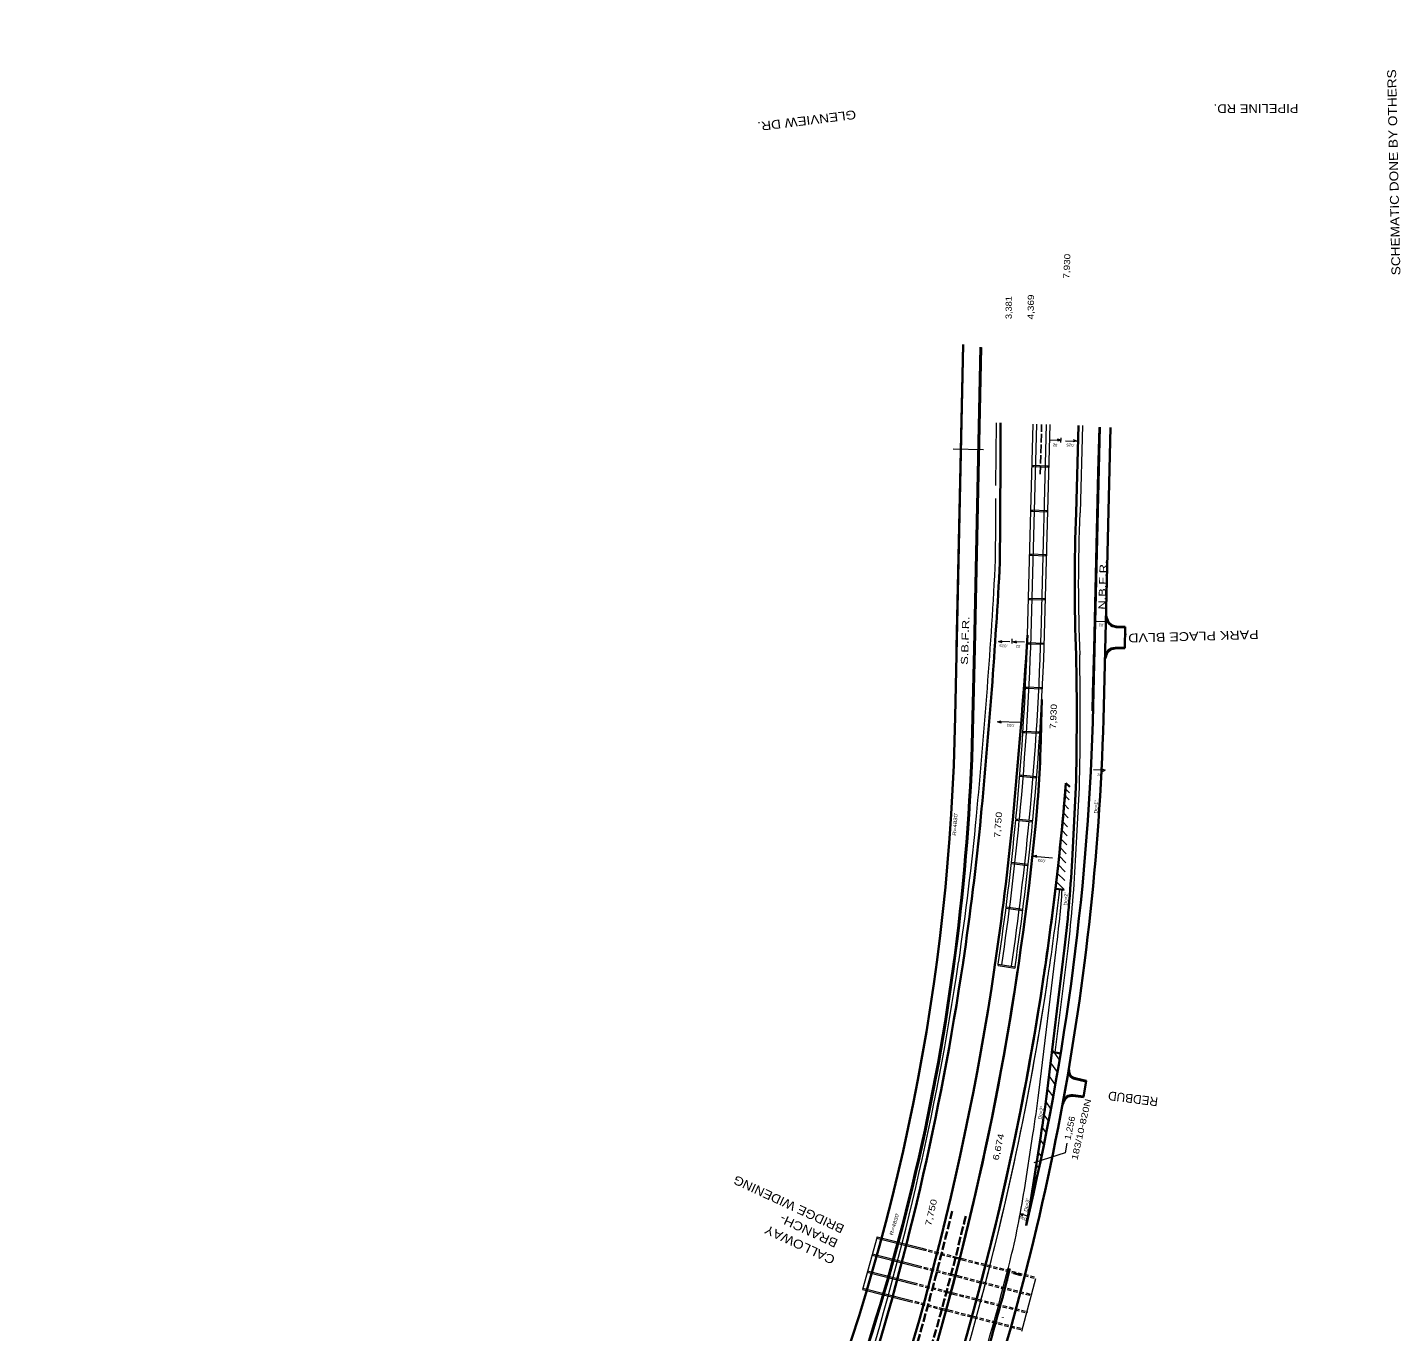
# Model space of a CAD drawing. Extents: x 2354993 to 2372084, y 6966390 to 6990057.
# Drawn here: x 2364099 to 2367196, y 6983254 to 6986197 of the extents above; entities that cross this region are included whole.
import ezdxf

# ---------------------------------------------------------------- set-up
doc = ezdxf.new("R2010")
doc.units = 0
doc.header["$LTSCALE"] = 3.2
doc.linetypes.add('LONG_DASHED', pattern=[7.5, 6, -1.5])
doc.linetypes.add('MEDIUM_DASHED', pattern=[4.5, 3, -1.5])
for name, color, linetype, lineweight in [('1', 7, 'Continuous', 13), ('11', 7, 'Continuous', 13), ('12', 7, 'Continuous', 13), ('13', 7, 'Continuous', 13), ('19', 7, 'Continuous', 13), ('2', 7, 'Continuous', 35), ('4', 7, 'Continuous', 13), ('40', 7, 'Continuous', 35), ('5', 7, 'Continuous', 35), ('6', 7, 'Continuous', 35), ('63', 7, 'Continuous', 35), ('7', 7, 'Continuous', 13), ('8', 7, 'Continuous', 13), ('9', 7, 'Continuous', 13)]:
    doc.layers.add(name, color=color, linetype=linetype, lineweight=lineweight)

msp = doc.modelspace()

# ---------------------------------------------------------------- linework, layer by layer
at = {"layer": '1', "lineweight": 35}
for p, q in [((2366503.056, 6984666.009), (2366518.337, 6985295.092)), ((2366527.049, 6984665.426), (2366542.33, 6985294.509))]:
    msp.add_line(p, q, dxfattribs=at)
at = {"layer": '1'}
for p, q in [((2366464.165, 6984330.073), (2366472.106, 6984481.877)), ((2366417.588, 6983883.842), (2366446.247, 6984118.848))]:
    msp.add_line(p, q, dxfattribs=at)
for points in [[(2366504.178, 6984794.577), (2366506.607, 6984894.547), (2366509.035, 6984994.518), (2366511.463, 6985094.488), (2366513.892, 6985194.459), (2366516.32, 6985294.429)], [(2366500.792, 6984655.165), (2366501.75, 6984694.606), (2366504.178, 6984794.577)]]:
    msp.add_lwpolyline(points, dxfattribs=at)
for centre, radius, start, end in [((2370574.042, 6984940.976), 4104.509, 177.76241, 182.23376), ((2359312.852, 6984644.469), 7161.104, 358.6944, 1.09115), ((2363580.688, 6984468.307), 2886.789, 353.04704, 357.25725), ((2359877.328, 6985028.057), 6596.25, 337.9611, 351.54396)]:
    msp.add_arc(centre, radius, start, end, dxfattribs=at)
at = {"layer": '1', "lineweight": 35}
msp.add_arc((2360811.157, 6984804.27), 5681.578, 345.37481, 345.37817, dxfattribs=at)
at = {"layer": '11'}
for p, q in [((2366538.791, 6984856.255), (2366530.724, 6984854.262)), ((2366529.954, 6984521.156), (2366503.645, 6984521.922)), ((2366523.004, 6984523.998), (2366529.954, 6984521.156)), ((2366523.876, 6984518.238), (2366529.954, 6984521.156))]:
    msp.add_line(p, q, dxfattribs=at)
msp.add_lwpolyline([(2366510.454, 6984857.25), (2366538.791, 6984856.255), (2366530.884, 6984858.81)], dxfattribs=at)
at = {"layer": '12'}
for p, q in [((2366364.888, 6985208.936), (2366364.805, 6985205.936)), ((2366364.805, 6985205.936), (2366403.044, 6985204.915)), ((2366364.888, 6985208.936), (2366403.118, 6985207.914)), ((2366367.987, 6985208.85), (2366367.904, 6985205.85)), ((2366399.945, 6985204.992), (2366400.019, 6985207.991)), ((2366403.044, 6985204.915), (2366403.118, 6985207.914)), ((2366362.436, 6985108.243), (2366362.353, 6985105.243)), ((2366362.353, 6985105.243), (2366400.592, 6985104.222)), ((2366362.436, 6985108.243), (2366400.666, 6985107.221)), ((2366365.535, 6985108.157), (2366365.452, 6985105.157)), ((2366397.493, 6985104.299), (2366397.567, 6985107.298)), ((2366400.592, 6985104.222), (2366400.666, 6985107.221)), ((2366359.998, 6985008.861), (2366359.915, 6985005.861)), ((2366359.915, 6985005.861), (2366398.154, 6985004.84)), ((2366359.998, 6985008.861), (2366398.228, 6985007.839)), ((2366363.097, 6985008.775), (2366363.014, 6985005.775)), ((2366395.055, 6985004.917), (2366395.129, 6985007.916)), ((2366398.154, 6985004.84), (2366398.228, 6985007.839)), ((2366357.049, 6984909.117), (2366356.966, 6984906.117)), ((2366356.966, 6984906.117), (2366395.205, 6984905.096)), ((2366357.049, 6984909.117), (2366395.279, 6984908.095)), ((2366360.148, 6984909.031), (2366360.065, 6984906.031)), ((2366392.106, 6984905.173), (2366392.18, 6984908.172)), ((2366395.205, 6984905.096), (2366395.279, 6984908.095)), ((2366354.588, 6984808.904), (2366354.505, 6984805.904)), ((2366354.505, 6984805.904), (2366392.744, 6984804.883)), ((2366354.588, 6984808.904), (2366392.818, 6984807.882)), ((2366357.687, 6984808.818), (2366357.604, 6984805.818)), ((2366389.645, 6984804.96), (2366389.719, 6984807.959)), ((2366392.744, 6984804.883), (2366392.818, 6984807.882)), ((2366350.209, 6984708.655), (2366350.126, 6984705.655)), ((2366350.126, 6984705.655), (2366388.365, 6984704.634)), ((2366350.209, 6984708.655), (2366388.439, 6984707.633)), ((2366353.308, 6984708.569), (2366353.225, 6984705.569)), ((2366385.266, 6984704.711), (2366385.34, 6984707.71)), ((2366388.365, 6984704.634), (2366388.439, 6984707.633)), ((2366344.53, 6984608.98), (2366344.406, 6984605.981)), ((2366344.406, 6984605.981), (2366382.629, 6984604.439)), ((2366344.53, 6984608.98), (2366382.743, 6984607.436)), ((2366347.628, 6984608.852), (2366347.504, 6984605.853)), ((2366379.531, 6984604.558), (2366379.646, 6984607.555)), ((2366382.629, 6984604.439), (2366382.743, 6984607.436)), ((2366338.161, 6984510.231), (2366337.864, 6984507.244)), ((2366338.161, 6984510.231), (2366376.221, 6984506.482)), ((2366341.246, 6984509.924), (2366340.949, 6984506.937)), ((2366337.864, 6984507.244), (2366375.933, 6984503.496)), ((2366372.847, 6984503.794), (2366373.135, 6984506.78)), ((2366375.933, 6984503.496), (2366376.221, 6984506.482)), ((2366328.743, 6984410.781), (2366328.446, 6984407.794)), ((2366328.446, 6984407.794), (2366366.515, 6984404.046)), ((2366328.743, 6984410.781), (2366366.803, 6984407.032)), ((2366331.828, 6984410.474), (2366331.531, 6984407.487)), ((2366363.429, 6984404.344), (2366363.717, 6984407.33)), ((2366366.515, 6984404.046), (2366366.803, 6984407.032)), ((2366318.344, 6984310.299), (2366356.373, 6984306.191)), ((2366318.666, 6984313.282), (2366356.695, 6984309.174)), ((2366306.287, 6984209.38), (2366344.232, 6984204.566)), ((2366306.665, 6984212.356), (2366344.611, 6984207.542)), ((2366288.504, 6984080.134), (2366288.942, 6984083.102)), ((2366288.504, 6984080.134), (2366326.343, 6984074.539)), ((2366288.942, 6984083.102), (2366326.781, 6984077.507)), ((2366326.781, 6984077.507), (2366326.343, 6984074.539)), ((2366015.164, 6983465.056), (2366116.698, 6983439.228)), ((2366015.904, 6983467.964), (2366117.457, 6983442.131)), ((2366004.286, 6983426.55), (2366106.578, 6983400.527)), ((2366005.097, 6983429.441), (2366107.337, 6983403.431)), ((2366186.244, 6983424.631), (2366208.214, 6983419.041)), ((2366185.481, 6983421.728), (2366207.447, 6983416.14)), ((2366306.379, 6983394.068), (2366312.798, 6983392.434)), ((2365993.478, 6983388.025), (2366096.459, 6983361.827)), ((2365994.288, 6983390.915), (2366097.218, 6983364.731)), ((2366175.316, 6983383.04), (2366197.226, 6983377.466)), ((2366176.078, 6983385.942), (2366197.993, 6983380.366)), ((2366305.608, 6983391.166), (2366312.143, 6983389.503)), ((2366323.39, 6983384.946), (2366339.177, 6983380.553)), ((2366324.132, 6983387.855), (2366339.955, 6983383.452)), ((2366342.248, 6983255.14), (2366373.814, 6983374.03)), ((2365982.67, 6983349.503), (2366086.339, 6983323.127)), ((2365983.481, 6983352.393), (2366087.098, 6983326.03)), ((2366165.15, 6983344.352), (2366187.006, 6983338.792)), ((2366165.913, 6983347.255), (2366187.773, 6983341.694)), ((2366295.329, 6983352.508), (2366303.407, 6983350.453)), ((2366296.1, 6983355.408), (2366304.062, 6983353.382)), ((2366154.985, 6983305.663), (2366176.785, 6983300.117)), ((2366155.748, 6983308.565), (2366177.552, 6983303.018)), ((2366285.049, 6983313.848), (2366294.672, 6983311.4)), ((2366285.821, 6983316.75), (2366295.327, 6983314.331)), ((2366274.77, 6983275.189), (2366285.936, 6983272.348)), ((2366275.541, 6983278.088), (2366286.591, 6983275.277))]:
    msp.add_line(p, q, dxfattribs=at)
at = {"layer": '12', "linetype": 'MEDIUM_DASHED'}
for p, q in [((2366116.698, 6983439.227), (2366185.481, 6983421.728)), ((2366117.457, 6983442.13), (2366186.244, 6983424.631)), ((2366106.578, 6983400.528), (2366175.316, 6983383.04)), ((2366107.337, 6983403.43), (2366176.078, 6983385.942)), ((2366207.447, 6983416.139), (2366369.811, 6983374.832)), ((2366208.214, 6983419.041), (2366371.427, 6983377.518)), ((2366096.458, 6983361.827), (2366165.15, 6983344.351)), ((2366097.218, 6983364.731), (2366165.913, 6983347.255)), ((2366197.226, 6983377.466), (2366360.946, 6983335.815)), ((2366197.993, 6983380.367), (2366360.785, 6983338.95)), ((2366187.006, 6983338.791), (2366354.02, 6983296.302)), ((2366187.773, 6983341.694), (2366355.61, 6983298.995)), ((2366086.339, 6983323.127), (2366154.985, 6983305.663)), ((2366087.098, 6983326.031), (2366155.748, 6983308.565)), ((2366176.785, 6983300.117), (2366343.594, 6983257.678)), ((2366177.552, 6983303.018), (2366344.357, 6983260.58))]:
    msp.add_line(p, q, dxfattribs=at)
at = {"layer": '12'}
for radius, start, end in [(6480.875, 351.616, 354.50799), (6488.875, 351.616, 354.50799), (6511.125, 351.61584, 354.50723), (6519.125, 351.61584, 354.50723)]:
    msp.add_arc((2359877.328, 6985028.058), radius, start, end, dxfattribs=at)
at = {"layer": '19'}
for p, q in [((2366430.521, 6985265.56), (2366422.451, 6985263.573)), ((2366430.174, 6985260.343), (2366430.481, 6985271.185)), ((2366466.196, 6985263.41), (2366458.126, 6985261.423)), ((2366289.386, 6984811.585), (2366297.456, 6984813.571)), ((2366319.615, 6984817.313), (2366319.461, 6984806.469)), ((2366322.246, 6984810.631), (2366330.316, 6984812.617)), ((2366287.333, 6984630.065), (2366295.39, 6984632.098)), ((2366376.305, 6984328.318), (2366368.138, 6984326.78)), ((2366368.138, 6984326.78), (2366411.423, 6984322.823)), ((2366375.889, 6984323.785), (2366368.138, 6984326.78)), ((2366337.6, 6983520.462), (2366344.344, 6983515.613)), ((2366337.6, 6983520.462), (2366345.892, 6983519.893)), ((2366354.54, 6983514.355), (2366337.6, 6983520.462))]:
    msp.add_line(p, q, dxfattribs=at)
for points in [[(2366404.755, 6985266.491), (2366430.521, 6985265.56), (2366422.62, 6985268.122)], [(2366440.43, 6985264.341), (2366466.196, 6985263.41), (2366458.295, 6985265.972)], [(2366315.152, 6984810.653), (2366289.386, 6984811.585), (2366297.287, 6984809.023)], [(2366348.012, 6984809.699), (2366322.246, 6984810.631), (2366330.147, 6984808.069)], [(2366339.317, 6984628.497), (2366287.333, 6984630.065), (2366295.252, 6984627.549)]]:
    msp.add_lwpolyline(points, dxfattribs=at)
at = {"layer": '2'}
for p, q in [((2366191.602, 6984641.522), (2366209.421, 6985481.658)), ((2366194.919, 6984797.945), (2366209.421, 6985481.658)), ((2366234.353, 6984795.684), (2366248.866, 6985475.047)), ((2366235.853, 6984795.652), (2366250.366, 6985475.015)), ((2366533.393, 6984866.222), (2366532.269, 6984872.365)), ((2366574.915, 6984842.827), (2366554.717, 6984843.989)), ((2366575.001, 6984844.324), (2366554.803, 6984845.486)), ((2366574.75, 6984796.484), (2366575.001, 6984844.324)), ((2366231.093, 6984640.684), (2366234.353, 6984795.684)), ((2366232.593, 6984640.652), (2366235.853, 6984795.652)), ((2366552.445, 6984796.946), (2366574.68, 6984797.983)), ((2366552.515, 6984795.448), (2366574.75, 6984796.484)), ((2366531.595, 6984775.836), (2366529.681, 6984771.371)), ((2366456.176, 6984330.491), (2366464.117, 6984482.295)), ((2366456.176, 6984330.491), (2366464.117, 6984482.295)), ((2366449.098, 6983843.616), (2366448.408, 6983847.851)), ((2366487.173, 6983818.766), (2366461.659, 6983824.757)), ((2366487.516, 6983820.226), (2366462.002, 6983826.217)), ((2366480.99, 6983782.813), (2366487.516, 6983820.226)), ((2366436.219, 6983770.765), (2366434.12, 6983767.703)), ((2366457.408, 6983786.42), (2366480.99, 6983782.813)), ((2366457.635, 6983787.903), (2366481.217, 6983784.295)), ((2366299.124, 6983285.604), (2366299.2, 6983286.601))]:
    msp.add_line(p, q, dxfattribs=at)
at = {"layer": '2', "lineweight": 13}
for p, q in [((2366355.875, 6984854.36), (2366367.65, 6985301.542)), ((2366363.872, 6984854.149), (2366375.647, 6985301.331)), ((2366386.165, 6984855.466), (2366397.891, 6985300.747)), ((2366394.162, 6984855.255), (2366405.888, 6985300.536)), ((2366015.905, 6983467.966), (2365982.67, 6983349.503))]:
    msp.add_line(p, q, dxfattribs=at)
at = {"layer": '2'}
for centre, radius, start, end in [((2370574.042, 6984940.976), 4112.509, 177.76241, 182.23376), ((2366556.863, 6984869.035), 25.138, 186.83461, 265.10234), ((2366556.863, 6984869.035), 23.638, 186.83461, 265.10234), ((2366552.807, 6984774.171), 22.778, 90.91053, 175.51359), ((2366552.807, 6984774.171), 21.278, 90.91053, 175.51359), ((2346853.406, 6985149.675), 19539.408, 358.20923, 358.62401), ((2361244.215, 6984746.454), 4988, 335.74923, 358.78496), ((2361244.215, 6984746.454), 4989.5, 335.74923, 358.78496), ((2361361.727, 6984722.767), 4830.559, 338.17176, 359.03629), ((2359877.328, 6985028.058), 6586.25, 353.24333, 355.09856), ((2359877.328, 6985028.058), 6586.25, 354.48323, 355.18157), ((2359877.328, 6985028.058), 6401.75, 351.54561, 354.5185), ((2359877.328, 6985028.058), 6473.75, 351.54561, 354.5185), ((2359877.328, 6985028.058), 6586.25, 351.52586, 353.24333), ((2359877.328, 6985028.058), 6473.75, 337.9611, 351.54233), ((2359877.328, 6985028.057), 6526.25, 337.9611, 351.54396), ((2359877.328, 6985028.057), 6586.25, 337.9611, 351.54396), ((2366464.179, 6983841.321), 16.755, 171.34788, 262.00973), ((2366464.179, 6983841.321), 15.255, 171.34788, 262.00973), ((2366455.784, 6983766.447), 21.536, 85.07046, 167.55399), ((2366455.784, 6983766.447), 20.036, 85.07046, 167.55399)]:
    msp.add_arc(centre, radius, start, end, dxfattribs=at)
at = {"layer": '2', "lineweight": 13}
for radius, start, end in [(6480.875, 354.53443, 358.4642), (6488.875, 354.53443, 358.4642), (6511.125, 354.53369, 358.48108), (6519.125, 354.53369, 358.48108)]:
    msp.add_arc((2359877.328, 6985028.058), radius, start, end, dxfattribs=at)
at = {"layer": '2', "linetype": 'LONG_DASHED'}
for centre, radius, end in [((2359877.328, 6985028.058), 6483.75, 346.60187), ((2359877.328, 6985028.057), 6516.25, 346.60718)]:
    msp.add_arc(centre, radius, 337.9611, end, dxfattribs=at)
at = {"layer": '2'}
msp.add_ellipse((2359801.786, 6985036.219), major_axis=(6478.123, 0), ratio=0.996776, start_param=5.97499933, end_param=6.13557103, dxfattribs=at)
at = {"layer": '4'}
msp.add_line((2366283.609, 6985162.922), (2366284.777, 6985305.032), dxfattribs=at)
at = {"layer": '4', "lineweight": 35}
for p, q in [((2366293.961, 6985234.465), (2366294.256, 6985304.512)), ((2366293.087, 6985079.285), (2366293.961, 6985234.465)), ((2366292.754, 6984989.792), (2366293.087, 6985079.285))]:
    msp.add_line(p, q, dxfattribs=at)
at = {"layer": '4'}
msp.add_lwpolyline([(2366282.681, 6984988.24), (2366282.785, 6985022.102), (2366283.108, 6985052.593), (2366283.2, 6985087.074), (2366283.645, 6985133.964)], dxfattribs=at)
for centre, radius, start, end in [((2352371.567, 6985744.582), 13931.634, 354.53186, 356.91694), ((2359877.328, 6985028.058), 6391.75, 351.54561, 354.51414), ((2359877.328, 6985028.058), 6391.75, 342.25932, 351.54233)]:
    msp.add_arc(centre, radius, start, end, dxfattribs=at)
at = {"layer": '4', "lineweight": 35}
for radius, end in [(13941.634, 356.89653), (14013.634, 356.24046)]:
    msp.add_arc((2352371.567, 6985744.582), radius, 354.53186, end, dxfattribs=at)
at = {"layer": '40', "linetype": 'LONG_DASHED', "lineweight": 25}
msp.add_line((2366383.808, 6985188.613), (2366386.769, 6985301.039), dxfattribs=at)
at = {"layer": '40'}
msp.add_line((2366464.669, 6985101.543), (2366469.865, 6985298.851), dxfattribs=at)
at = {"layer": '40', "lineweight": 13}
msp.add_line((2366474.666, 6985101.28), (2366479.862, 6985298.588), dxfattribs=at)
at = {"layer": '5', "lineweight": 13}
for p, q in [((2366449.462, 6984470.141), (2366440.66, 6984479.098)), ((2366448.633, 6984454.299), (2366439.358, 6984463.738)), ((2366446.508, 6984413.673), (2366435.865, 6984424.498)), ((2366447.571, 6984433.986), (2366437.638, 6984444.092)), ((2366444.382, 6984373.037), (2366432.156, 6984385.475)), ((2366445.445, 6984393.356), (2366434.037, 6984404.961)), ((2366443.32, 6984352.721), (2366430.223, 6984366.045)), ((2366441.214, 6984312.071), (2366426.198, 6984327.346)), ((2366442.257, 6984332.407), (2366428.236, 6984346.67)), ((2366440.039, 6984291.868), (2366424.107, 6984308.074)), ((2366437.29, 6984251.873), (2366419.772, 6984269.691)), ((2366438.73, 6984271.803), (2366421.965, 6984288.857)), ((2366380.341, 6983793.189), (2366420.438, 6984121.995)), ((2366410.241, 6983889.678), (2366426.954, 6983866.372)), ((2366406.664, 6983860.347), (2366422.248, 6983838.616)), ((2366403.087, 6983831.017), (2366417.429, 6983811.018)), ((2366399.51, 6983801.686), (2366412.498, 6983783.576)), ((2366395.881, 6983772.428), (2366407.456, 6983756.287)), ((2366392.013, 6983743.503), (2366402.306, 6983729.15)), ((2366387.898, 6983714.923), (2366397.049, 6983702.162)), ((2366347.754, 6983573.93), (2366367.202, 6983698.615)), ((2366383.555, 6983686.66), (2366391.686, 6983675.321)), ((2366379.158, 6983658.472), (2366386.219, 6983648.626)), ((2366374.762, 6983630.284), (2366380.649, 6983622.074)), ((2366370.365, 6983602.096), (2366374.978, 6983595.664)), ((2366365.969, 6983573.908), (2366369.206, 6983569.393)), ((2366293.589, 6983328.522), (2366311.43, 6983397.183)), ((2366311.209, 6983395.611), (2366314.99, 6983410.926))]:
    msp.add_line(p, q, dxfattribs=at)
at = {"layer": '5'}
for p, q in [((2366450.136, 6984483.026), (2366441.695, 6984491.613)), ((2366417.835, 6984253.165), (2366437.241, 6984251.233)), ((2366398.208, 6983791.01), (2366438.306, 6984119.816)), ((2366429.523, 6983881.883), (2366409.787, 6983885.123)), ((2366365.539, 6983571.156), (2366384.987, 6983695.841)), ((2366297.461, 6983327.516), (2366315.301, 6983396.177))]:
    msp.add_line(p, q, dxfattribs=at)
at = {"layer": '5', "lineweight": 13}
msp.add_lwpolyline([(2366443.757, 6983679.208), (2366440.171, 6983657.357), (2366369.094, 6983635.235)], dxfattribs=at)
at = {"layer": '5'}
for centre, radius, start, end in [((2360811.157, 6984804.27), 5717.578, 339.9908, 358.60851), ((2360811.157, 6984804.27), 5693.578, 346.6878, 358.60851), ((2362514.248, 6984735.032), 3873.983, 355.57895, 357.10053), ((2359877.328, 6985028.058), 6586.25, 344.87929, 355.32812), ((2359877.328, 6985028.058), 6526.25, 344.87929, 354.79857), ((2363580.688, 6984468.302), 2878.789, 353.04712, 357.25735), ((2363540.59, 6984139.496), 2878.789, 351.1347, 353.04712), ((2364464.664, 6983867.646), 1923.859, 348.77927, 351.1347), ((2360811.157, 6984804.27), 5681.578, 339.99081, 344.99116)]:
    msp.add_arc(centre, radius, start, end, dxfattribs=at)
at = {"layer": '5', "lineweight": 13}
for centre, radius, start, end in [((2359877.328, 6985028.058), 6596.25, 351.52586, 353.24495), ((2363580.688, 6984468.302), 2860.789, 353.04712, 355.65632), ((2359877.328, 6985028.057), 6596.25, 344.87918, 351.54396), ((2363540.59, 6984139.496), 2860.789, 351.1347, 353.04712), ((2364464.664, 6983867.646), 1905.859, 346.1347, 351.1347), ((2360811.157, 6984804.27), 5677.578, 339.99081, 344.99116)]:
    msp.add_arc(centre, radius, start, end, dxfattribs=at)
at = {"layer": '6'}
msp.add_arc((2359312.852, 6984644.469), 7153.104, 358.6944, 1.09115, dxfattribs=at)
at = {"layer": '8'}
msp.add_line((2366255.472, 6985244.095), (2366187.376, 6985244.954), dxfattribs=at)
at = {"layer": '9'}
msp.add_arc((2360722.521, 6984327.136), 5729.573, 359.50797, 359.50797, dxfattribs=at)

# ---------------------------------------------------------------- texts
at = {"layer": '13'}
for s, height, rotation, width, p in [('GLENVIEW DR.', 20, 187.098, 1.15, (2365966.815, 6986010.487)), ('PIPELINE RD.', 20, 180.198, 1.1, (2366966.075, 6986024.063)), ('N.B.F.R.', 16, 88.194, 1.35, (2366530.474, 6984883.069)), ('S.B.F.R.', 16, 88.194, 1.35, (2366220.301, 6984758.646)), ('PARK PLACE BLVD.', 20, 181.585, 1.2, (2366875.957, 6984837.023)), ('7,930', 14, 87.365, 1.2, (2366418.843, 6984613.738)), ('7,750', 14, 85.224, 1.25, (2366292.854, 6984367.979)), ('183/10-820N ', 14, 77.104, 1.3, (2366467.227, 6983640.224)), ('1,256', 14, 77.763, 1.15, (2366451.533, 6983685.835)), ('6,674', 14, 77.487, 1.3, (2366289.228, 6983639.46)), ('BRIDGE WIDENING', 20, 155.121, 1.1, (2365943.471, 6983493.184)), ('7,750', 14, 76.953, 1.3, (2366137.322, 6983491.861)), ('CALLOWAY', 20, 155.121, 1.15, (2365922.831, 6983423.18)), ('BRANCH-', 20, 155.121, 1.15, (2365929.131, 6983460.948))]:
    msp.add_text(s, height=height, rotation=rotation, dxfattribs=dict(at, width=width)).set_placement(p)
msp.add_text('REDBUD', height=20, rotation=172.734, dxfattribs=at).set_placement((2366650.238, 6983782.238))
at = {"layer": '19'}
for s, height, rotation, width, p in [('.02', 5.999, 177.853, 1.1, (2366424.573, 6985257.118)), ('.025', 6, 176.541, 1.2, (2366461.735, 6985256.76)), ('.02', 5.999, 177.689, 1.1, (2366527.861, 6984851.17)), ('.025', 5.999, 176.112, 1.2, (2366310.17, 6984803.739)), ('.02', 6, 179.189, 1.05, (2366340.492, 6984803.303)), ('.033', 5.999, 176.39, 1.2, (2366326.848, 6984624.444)), ('.02', 5.999, 175.689, 1.1, (2366524.98, 6984512.782)), ('Dc=1°', 8, 87.297, 0.95, (2366512.665, 6984423.288)), ('.033', 6, 172.955, 1.2, (2366396.927, 6984318.53)), ('Dc=2°', 8, 79.394, 1.05, (2366386.109, 6983732.411)), ('Dc=3°', 8, 79.394, 1.05, (2366354.312, 6983524.254)), ('.039', 6, 160.217, 1.25, (2366356.161, 6983508.93))]:
    msp.add_text(s, height=height, rotation=rotation, dxfattribs=dict(at, width=width)).set_placement(p)
msp.add_text('Dc=2°', height=8, rotation=87.297, dxfattribs=at).set_placement((2366444.683, 6984215.595))
at = {"layer": '63'}
for s, height, rotation, width, p in [('SCHEMATIC DONE BY OTHERS', 20, 91.231, 1.15, (2367196.197, 6985637.787)), ('7,930', 14, 87.365, 1.2, (2366449.31, 6985629.536)), ('4,369', 14, 89.12, 1.2, (2366368.747, 6985537.812)), ('3,381', 14, 89.847, 1.1, (2366319.343, 6985538.865))]:
    msp.add_text(s, height=height, rotation=rotation, dxfattribs=dict(at, width=width)).set_placement(p)
at = {"layer": '7', "width": 1.3}
for rotation, p in [(86.009, (2366193.607, 6984372.876)), (74.106, (2366051.268, 6983470.901))]:
    msp.add_text("R=4830'", height=8, rotation=rotation, dxfattribs=at).set_placement(p)

doc.saveas('drawing.dxf')
